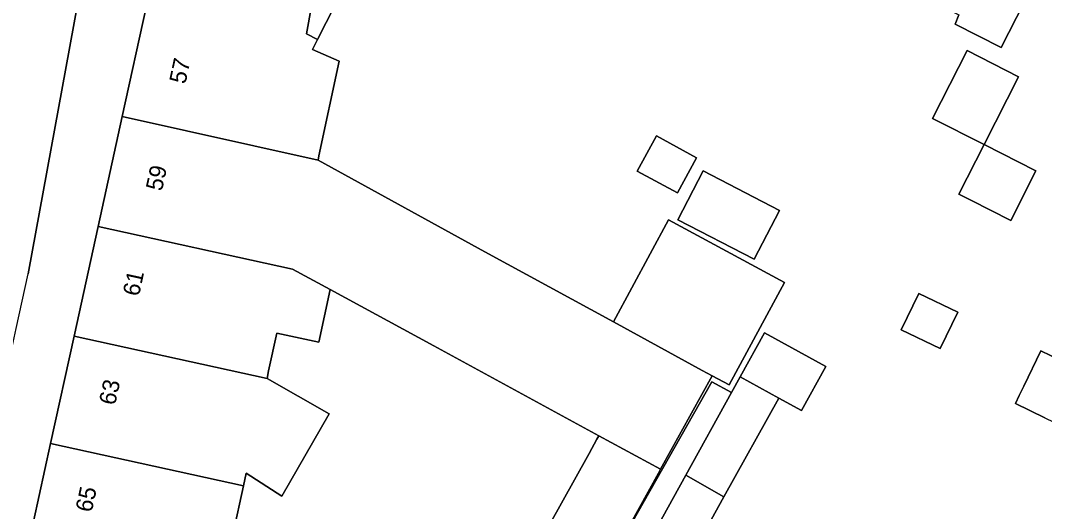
# Model space of a CAD drawing. Extents: x 160349 to 161355, y 381727 to 382854.
# Drawn here: x 160886.7 to 160947.9, y 382368 to 382397.3 of the extents above; entities that cross this region are included whole.
import ezdxf

# ---------------------------------------------------------------- set-up
doc = ezdxf.new("R2010")
doc.units = 0
for name, color, linetype in [('IMGEO_Erf', 7, 'Continuous'), ('IMGEO_Pand', 7, 'Continuous'), ('IMGEO_Pand_nummerreeks', 7, 'Continuous'), ('IMGEO_Terreindeel_zand', 7, 'Continuous'), ('IMGEO_Voetpad_open', 7, 'Continuous')]:
    doc.layers.add(name, color=color, linetype=linetype)

msp = doc.modelspace()

# ---------------------------------------------------------------- linework, layer by layer
at = {"layer": 'IMGEO_Erf'}
for points in [[(160964.859, 382360.589), (160972.84, 382376.279), (160981.996, 382396.364), (160920.092, 382427.927), (160914.362, 382428.677), (160913.551, 382429.345), (160896.195, 382431.129), (160894.761, 382429.245), (160891.566, 382407.153), (160890.782, 382401.963), (160887.151, 382382.179)], [(160907.546, 382402.296), (160904.447, 382396.167), (160904.149, 382395.578), (160905.735, 382394.883), (160904.532, 382389.221), (160904.478, 382388.965), (160914.45, 382383.487), (160922.12, 382379.3), (160925.409, 382385.396), (160932.342, 382381.655), (160929.036, 382375.53), (160928.035, 382376.071), (160924.947, 382370.491), (160924.816, 382370.254), (160921.926, 382365.031)], [(160948.941, 382402.841), (160945.301, 382395.694), (160942.543, 382397.093), (160942.765, 382397.637)], [(160887.135, 382365.811), (160888.496, 382372.03), (160889.899, 382378.445), (160891.332, 382384.993), (160892.77, 382391.561), (160894.218, 382398.18)], [(160905.193, 382381.23), (160904.523, 382378.079), (160902.019, 382378.627), (160901.524, 382376.364), (160901.427, 382375.921), (160905.148, 382373.808), (160902.302, 382368.885), (160900.189, 382370.265), (160900.023, 382369.506), (160898.785, 382363.848)], [(160918.253, 382367.063), (160920.668, 382371.429), (160921.143, 382372.287), (160921.259, 382372.496), (160911.392, 382377.86), (160905.193, 382381.23)], [(160916.56, 382355.517), (160928.015, 382375.716), (160929.177, 382375.074), (160929.698, 382376.016), (160931.153, 382378.646), (160934.809, 382376.625), (160933.354, 382373.994), (160932, 382374.743), (160928.731, 382368.836), (160925.897, 382363.715)], [(160947.899, 382373.572), (160946.151, 382374.418), (160946.379, 382374.89), (160946.658, 382375.466), (160947.672, 382377.562), (160949.405, 382376.723)]]:
    msp.add_lwpolyline(points, dxfattribs=at)
for points in [[(160941.2, 382391.45), (160943.257, 382395.505), (160946.328, 382393.947), (160944.272, 382389.892)], [(160924.692, 382390.416), (160927.098, 382389.104), (160925.951, 382387.001), (160923.545, 382388.312)], [(160944.272, 382389.892), (160947.373, 382388.319), (160945.872, 382385.359), (160943.484, 382386.571), (160943.089, 382386.771), (160942.771, 382386.933)], [(160927.487, 382388.322), (160932.051, 382385.956), (160930.537, 382383.037), (160925.973, 382385.404)], [(160939.319, 382378.823), (160940.371, 382380.997), (160942.697, 382379.871), (160941.645, 382377.698)]]:
    msp.add_lwpolyline(points, close=True, dxfattribs=at)
msp.add_arc((160651.883, 382431.729), 240.429, 341.69717, 348.10664, dxfattribs=at)
at = {"layer": 'IMGEO_Pand'}
for points in [[(160939.618, 382399.24), (160942.765, 382397.637), (160942.543, 382397.093), (160945.301, 382395.694), (160948.941, 382402.841), (160951.209, 382407.296), (160948.972, 382408.436), (160948.643, 382407.79), (160945.377, 382409.453), (160945.591, 382409.874), (160945.1, 382410.124), (160940.716, 382401.506)], [(160904.447, 382396.167), (160903.781, 382396.51), (160904.335, 382399.613), (160895.336, 382400.968), (160894.746, 382398.065), (160894.218, 382398.18), (160892.77, 382391.561), (160904.478, 382388.965), (160904.532, 382389.221), (160905.735, 382394.883), (160904.149, 382395.578)], [(160941.2, 382391.45), (160944.272, 382389.892), (160946.328, 382393.947), (160943.257, 382395.505)], [(160904.478, 382388.965), (160892.77, 382391.561), (160891.332, 382384.993), (160902.945, 382382.452), (160905.193, 382381.23), (160911.392, 382377.86), (160921.259, 382372.496), (160924.947, 382370.491), (160928.035, 382376.071), (160927.43, 382376.402), (160922.12, 382379.3), (160914.45, 382383.487)], [(160923.545, 382388.312), (160925.951, 382387.001), (160927.098, 382389.104), (160924.692, 382390.416)], [(160944.272, 382389.892), (160942.771, 382386.933), (160943.089, 382386.771), (160943.484, 382386.571), (160945.872, 382385.359), (160947.373, 382388.319)], [(160925.973, 382385.404), (160930.537, 382383.037), (160932.051, 382385.956), (160927.487, 382388.322)], [(160932.342, 382381.655), (160925.409, 382385.396), (160922.12, 382379.3), (160927.43, 382376.402), (160928.035, 382376.071), (160929.036, 382375.53)], [(160891.332, 382384.993), (160889.899, 382378.445), (160901.427, 382375.921), (160901.524, 382376.364), (160902.019, 382378.627), (160904.523, 382378.079), (160905.193, 382381.23), (160902.945, 382382.452)], [(160939.319, 382378.823), (160941.645, 382377.698), (160942.697, 382379.871), (160940.371, 382380.997)], [(160961.32, 382377.238), (160959.803, 382377.972), (160957.626, 382379.026), (160957.539, 382378.847), (160956.222, 382379.484), (160955.065, 382377.092), (160952.11, 382378.522), (160951.039, 382376.31), (160949.553, 382377.029), (160949.405, 382376.723), (160947.672, 382377.562), (160946.658, 382375.466), (160946.379, 382374.89), (160946.151, 382374.418), (160947.899, 382373.572), (160949.485, 382372.805), (160953.985, 382370.626), (160955.282, 382373.307), (160964.499, 382368.845), (160965.653, 382371.229), (160966.445, 382371.286), (160967.203, 382372.851), (160966.905, 382373.709), (160967.195, 382374.307)], [(160901.427, 382375.921), (160889.899, 382378.445), (160888.496, 382372.03), (160900.023, 382369.506), (160900.189, 382370.265), (160902.302, 382368.885), (160905.148, 382373.808)], [(160929.698, 382376.016), (160932, 382374.743), (160933.354, 382373.994), (160934.809, 382376.625), (160931.153, 382378.646)], [(160932, 382374.743), (160929.698, 382376.016), (160929.177, 382375.074), (160926.446, 382370.139), (160928.731, 382368.836)], [(160924.947, 382370.491), (160921.259, 382372.496), (160921.143, 382372.287), (160920.668, 382371.429), (160918.253, 382367.063), (160921.926, 382365.031), (160924.816, 382370.254)], [(160900.023, 382369.506), (160888.496, 382372.03), (160887.135, 382365.811), (160898.662, 382363.287), (160898.785, 382363.848)], [(160926.446, 382370.139), (160923.596, 382364.989), (160925.897, 382363.715), (160928.731, 382368.836)]]:
    msp.add_lwpolyline(points, close=True, dxfattribs=at)
at = {"layer": 'IMGEO_Terreindeel_zand'}
msp.add_lwpolyline([(160908.64, 382404.46), (160905.596, 382406.011), (160905.462, 382405.345), (160904.335, 382399.613), (160903.781, 382396.51), (160904.447, 382396.167), (160907.546, 382402.296)], close=True, dxfattribs=at)
at = {"layer": 'IMGEO_Voetpad_open'}
msp.add_lwpolyline([(160887.151, 382382.179), (160890.782, 382401.963), (160891.566, 382407.153), (160894.761, 382429.245)], dxfattribs=at)
msp.add_lwpolyline([(160926.446, 382370.139), (160929.177, 382375.074), (160928.015, 382375.716), (160916.56, 382355.517), (160910.772, 382344.924), (160917.041, 382341.499), (160922.876, 382338.311), (160922.595, 382337.752), (160926.929, 382335.576), (160927.408, 382335.303), (160928.132, 382336.579), (160916.64, 382343.101), (160912.492, 382345.446), (160914.337, 382348.709), (160920.017, 382358.696), (160919.971, 382358.721), (160921.208, 382360.969), (160921.285, 382360.926), (160923.596, 382364.989)], close=True, dxfattribs=at)
msp.add_arc((160651.883, 382431.729), 240.429, 341.69717, 348.10664, dxfattribs=at)

# ---------------------------------------------------------------- texts
at = {"layer": 'IMGEO_Pand_nummerreeks'}
for s, rotation, p in [('57', 77.65651, (160896.545, 382393.471)), ('59', 77.6587, (160895.144, 382387.072)), ('61', 77.65651, (160893.768, 382380.784)), ('63', 77.6587, (160892.344, 382374.274)), ('65', 77.6587, (160890.943, 382367.875))]:
    msp.add_text(s, height=1, rotation=rotation, dxfattribs=at).set_placement(p)

doc.saveas('drawing.dxf')
